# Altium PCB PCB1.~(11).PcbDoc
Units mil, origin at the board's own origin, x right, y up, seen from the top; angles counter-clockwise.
Board outline 2756 x 2756 mil, 4 copper layers (Top Layer, Internal Plane 1, Internal Plane 2, Bottom Layer), stack 18.2 mil thick; 14 components, 14 nets, 59 pads, 0 vias.
Unrouted connection lines stored in the file: 27.
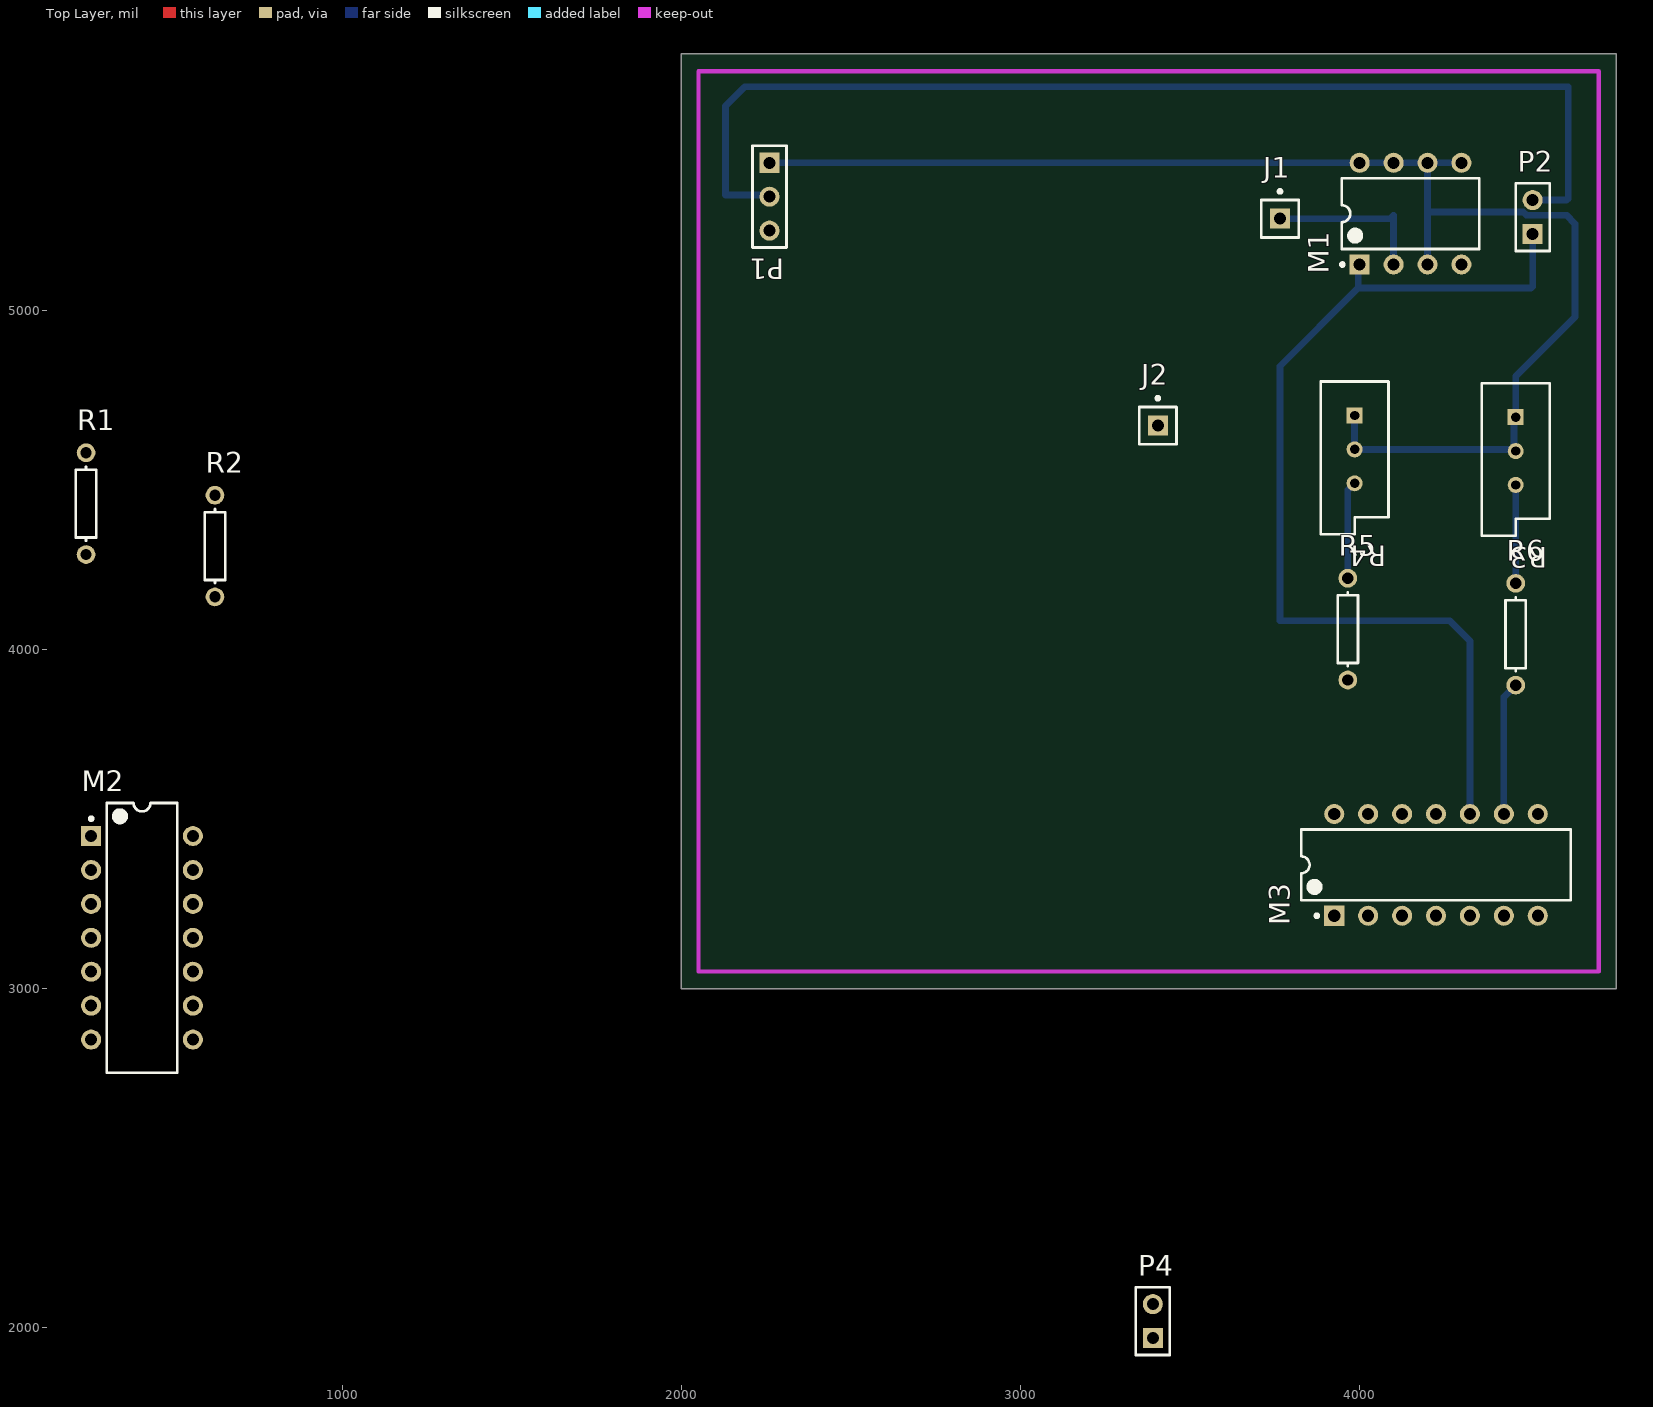
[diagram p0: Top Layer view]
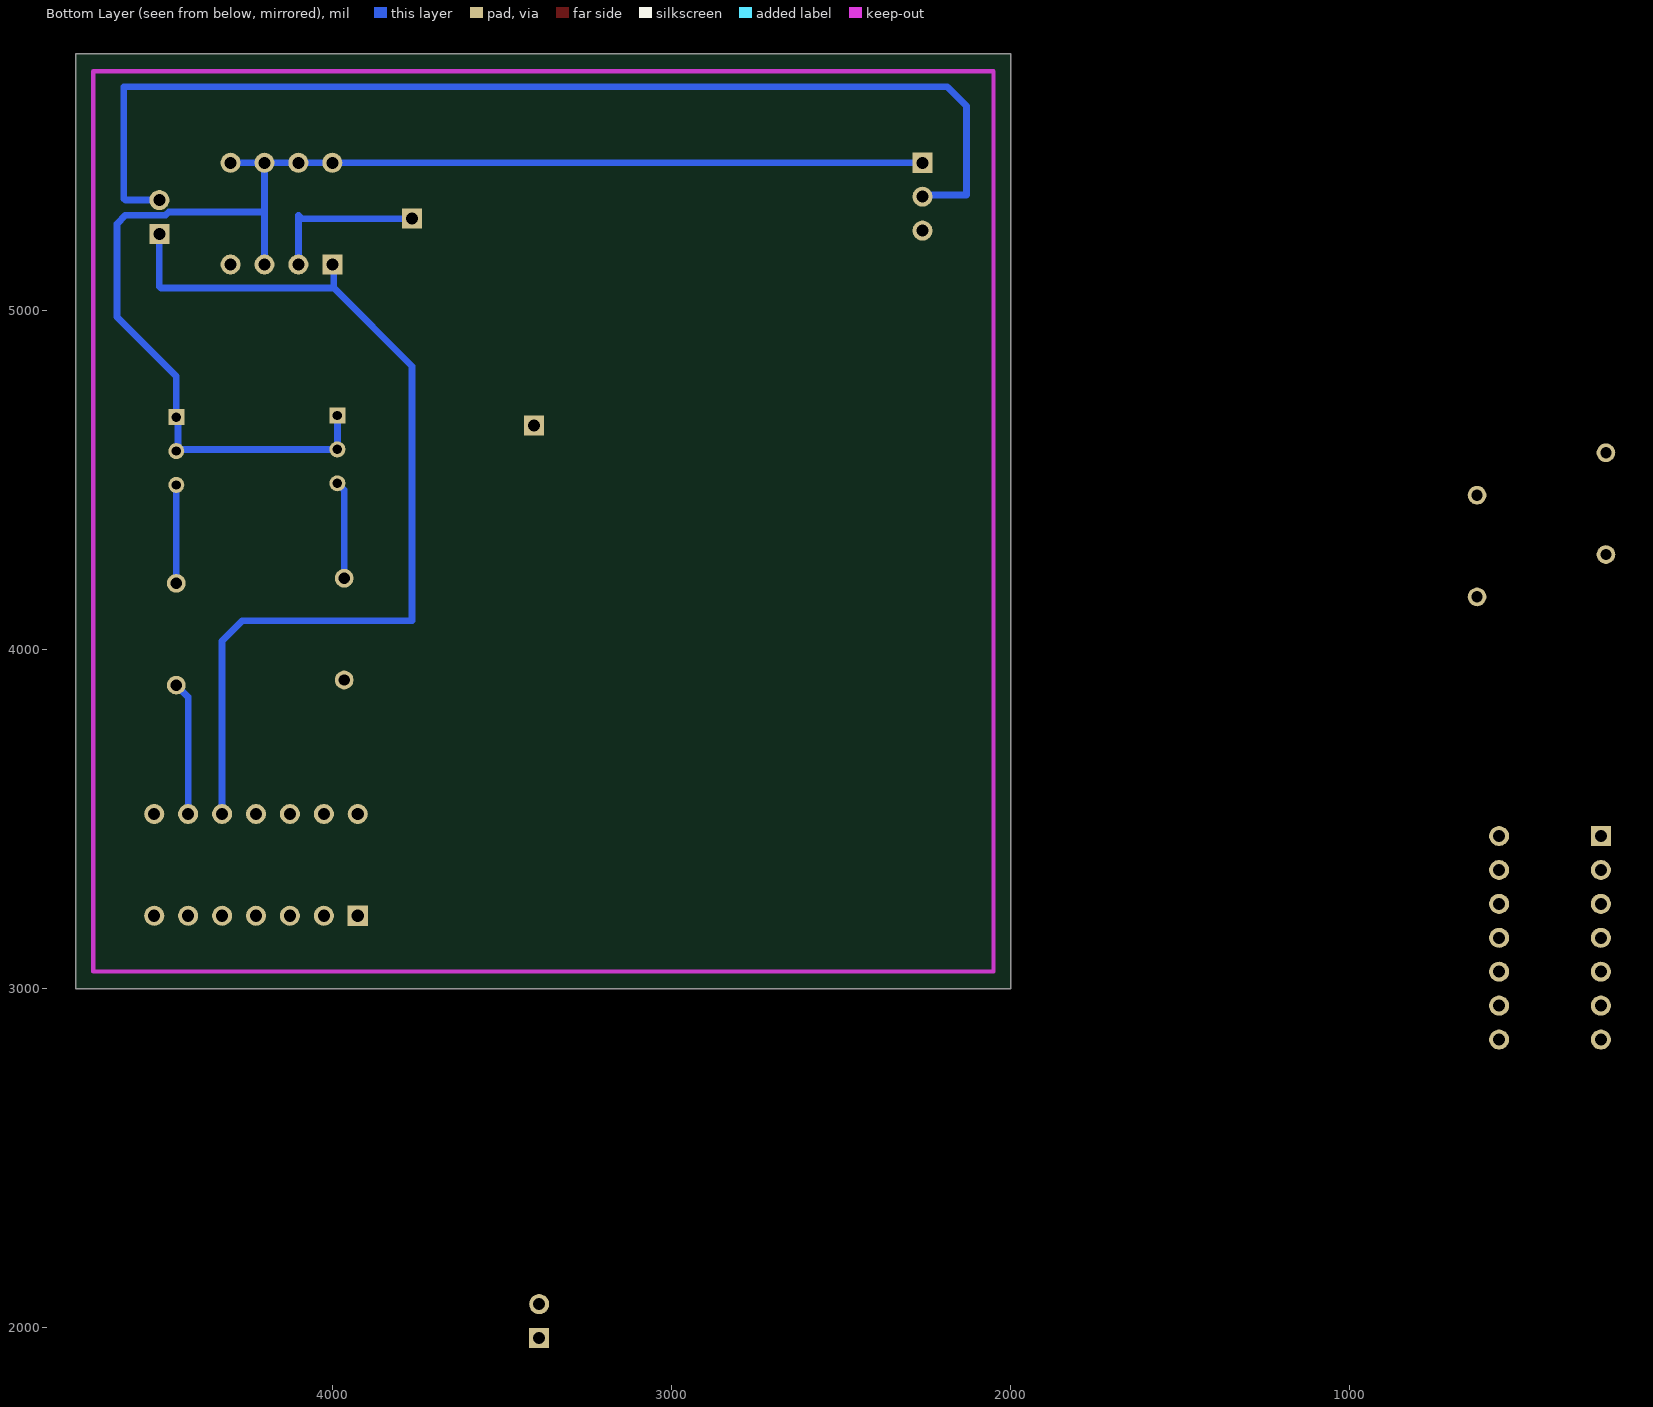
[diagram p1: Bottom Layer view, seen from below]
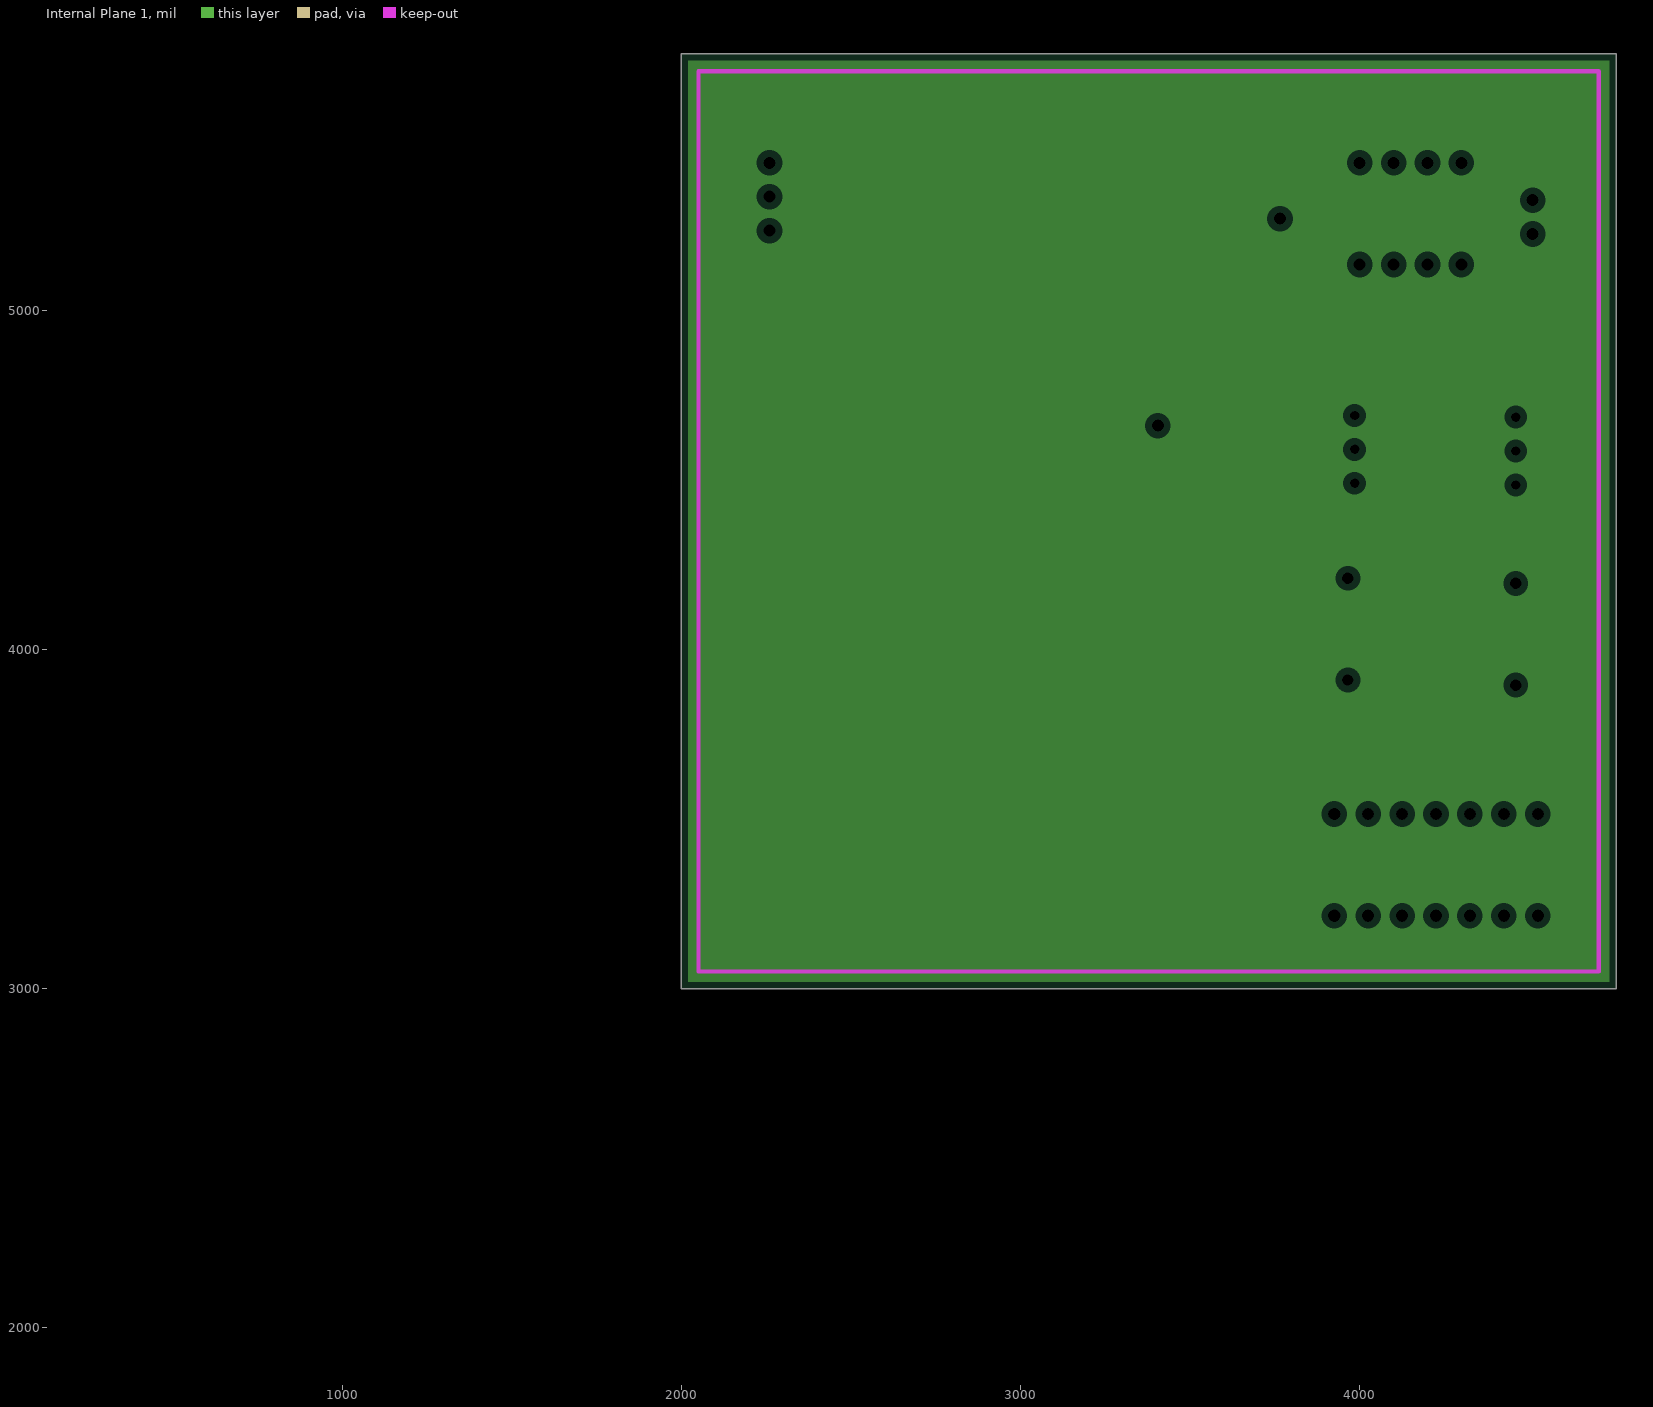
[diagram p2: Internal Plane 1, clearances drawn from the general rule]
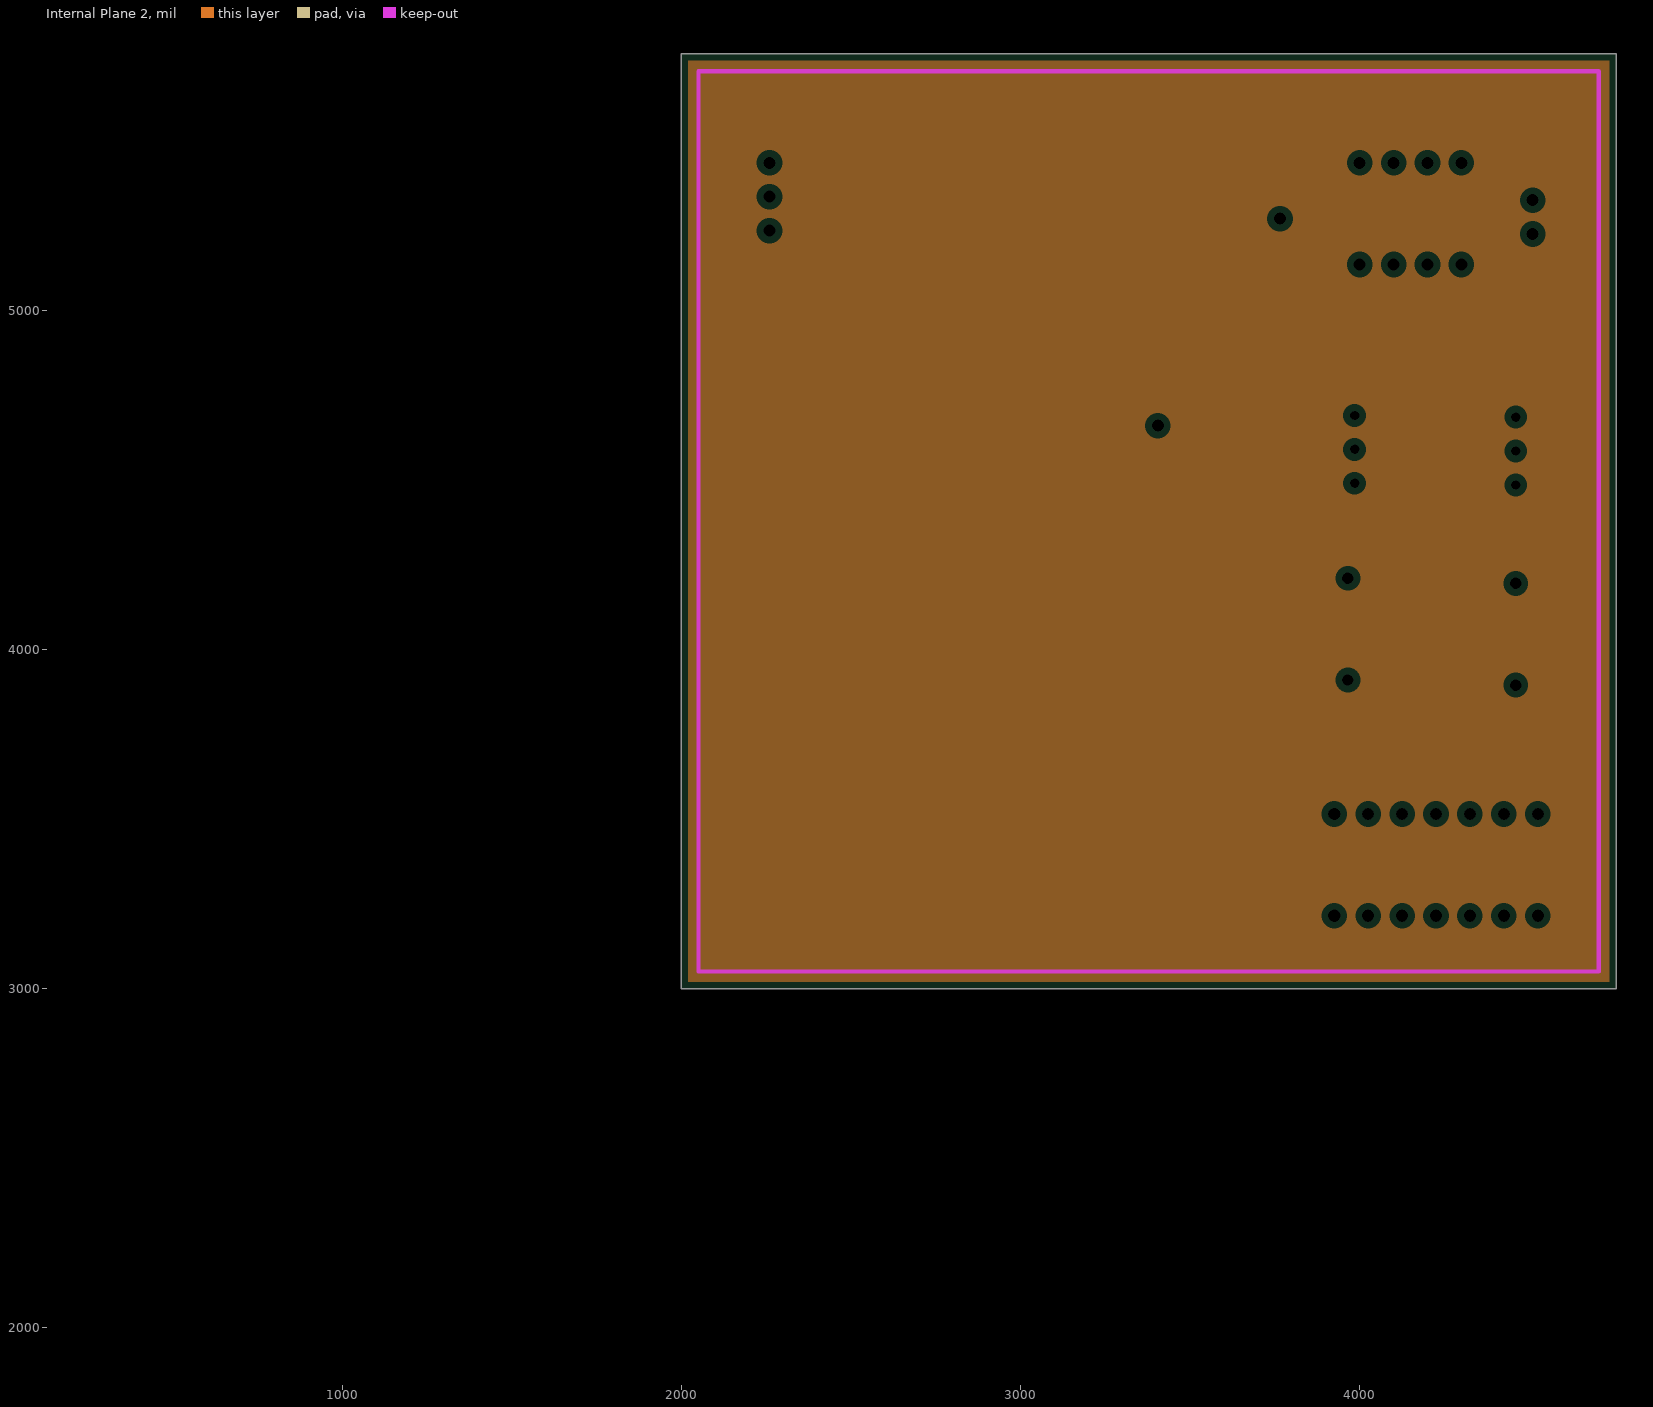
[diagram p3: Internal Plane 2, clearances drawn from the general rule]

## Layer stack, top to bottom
Top Solder: solder mask 0.4, Solder Resist, Dk 3.5
Top Layer: signal copper 1.4
Internal Plane 1: plane copper 1.4
Internal Plane 2: plane copper 1.4
Dielectric 1: dielectric 12.6, FR-4, Dk 4.8
Bottom Layer: signal copper 1.4
Bottom Solder: solder mask 0.4, Solder Resist, Dk 3.5

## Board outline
2000,3000 4756,3000 4756,5756 2000,5756

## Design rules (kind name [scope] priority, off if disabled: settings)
Clearance Clearance_1 [InNet('+5')] p1: gap=5
Clearance [All] p2: gap=30
PlaneClearance [All] p1: clearance=20
PlaneConnect [All] p1: planeconnectstyle=Relief reliefexpansion=20 reliefentries=4 reliefconductorwidth=10 reliefairgap=10
PolygonConnect [All] p1: connectstyle=Relief reliefconductorwidth=10 reliefentries=4 polygonreliefangle="90 Angle" airgapwidth=10
RoutingVias [All] p1: holewidth=32 width=62 viastyle="Through Hole" minholewidth=28 minwidth=50 maxholewidth=28 maxwidth=50
SolderMaskExpansion [All] p1: expansion=4
Width [All] p1: maxlimit=20 minlimit=8 preferedwidth=20 toplayer_minwidth=20 minimp=50.000000 maximp=50.000000 favimp=50.000000
28 further rules are at their usual default settings.

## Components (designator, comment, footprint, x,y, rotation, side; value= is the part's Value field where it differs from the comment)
J1 "Socket" PIN1 3765,5270 r0 top
J2 "Socket" PIN1 3405,4660 r0 top
M1 "ALD1117" DIP-8 4150,5285 r90 top
M2 "ALD1105" DIP-14 410,3150 r0 top
M3 "ALD1106" DIP-14 4225,3365 r90 top
P1 "Header 3" HDR1X3 2260,5435 r270 top
P2 "Header 2" HDR1X2 4510,5225 r90 top
P4 "Header 2" HDR1X2 3390,1970 r90 top
R1 "Res1" AXIAL-0.3 245,4430 r90 top
R2 "Res1" AXIAL-0.3 625,4305 r90 top
R3 "RPot" VR5 4460,4585 r270 top
R4 "RPot" VR5 3985,4590 r270 top
R5 "Res1" AXIAL-0.3 3965,4060 r90 top
R6 "Res1" AXIAL-0.3 4460,4045 r90 top

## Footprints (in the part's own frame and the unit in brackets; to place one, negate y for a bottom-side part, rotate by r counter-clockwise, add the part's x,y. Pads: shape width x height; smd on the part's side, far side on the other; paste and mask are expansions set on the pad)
AXIAL-0.3 [mm] "Axial Device, Thru-Hole; 2 Leads; 0.3 in Pin Spacing"
  round 1.4 hole 0.85: 1(-3.81,0) 2(3.81,0)
  silkscreen extent -2.77,-0.76 2.77,0.76
DIP-8 [mm] "DIP, 8-Pin, Row Spacing 7.62 mm, Pitch 2.54 mm"
  rect 1.5x1.5 hole 0.9: 1(-3.81,3.81)
  round 1.5 hole 0.9: 2(-3.81,1.27) 3(-3.81,-1.27) 4(-3.81,-3.81) 5(3.81,-3.81) 6(3.81,-1.27) 7(3.81,1.27) 8(3.81,3.81)
  silkscreen extent -3.93,-5.15 2.65,5.23, body extent -3.6,-5.15 3.6,5.15, height 5.33
DIP-14 [mm] "DIP, 14-Pin, Row Spacing 7.62 mm, Pitch 2.54 mm"
  rect 1.5x1.5 hole 0.9: 1(-3.81,7.62)
  round 1.5 hole 0.9: 2(-3.81,5.08) 3(-3.81,2.54) 4(-3.81,0) 5(-3.81,-2.54) 6(-3.81,-5.08) 7(-3.81,-7.62) 8(3.81,-7.62) 9(3.81,-5.08) 10(3.81,-2.54) 11(3.81,0) 12(3.81,2.54) 13(3.81,5.08) 14(3.81,7.62)
  silkscreen extent -3.93,-10.1 2.65,10.1, body extent -3.6,-10.1 3.6,10.1, height 5.08
HDR1X2 [mm] "Connector; Header; 2 Position"
  rect 1.5x1.5 hole 0.9: 1(0,0)
  round 1.5 hole 0.9: 2(2.54,0)
  silkscreen extent -1.27,-1.27 3.81,1.27
HDR1X3 [mm] "Connector; Header; 3 Position"
  rect 1.5x1.5 hole 0.9: 1(0,0)
  round 1.5 hole 0.9: 2(2.54,0) 3(5.08,0)
  silkscreen extent -1.27,-1.27 6.35,1.27
PIN1 [mm] "Connector; Plug"
  rect 1.5x1.5 hole 0.9: 1(0,0)
  silkscreen extent -1.4,-1.4 1.4,2.17
VR5 [mm] "Thru-Hole; 3 Leads"
  rect 1.2x1.2 hole 0.7: 1(-2.54,0)
  round 1.2 hole 0.7: 2(0,0) 3(2.54,0)
  silkscreen extent -5.08,-2.54 6.35,2.54

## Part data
M1: "Dual P-channel matched MOSFET array"
M2: "Dual P-channel and dual N-channel matched MOSFET array"
M3: "Quad N-channel matched MOSFET array"
P1: "Header, 3-Pin"
P2 P4: "Header, 2-Pin"
R1 R2 R5 R6: "Resistor"
R3 R4: "Potentiometer"

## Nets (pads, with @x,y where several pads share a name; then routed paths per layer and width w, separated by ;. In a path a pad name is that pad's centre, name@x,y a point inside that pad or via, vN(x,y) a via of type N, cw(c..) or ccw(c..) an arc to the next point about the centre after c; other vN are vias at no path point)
+5: M1.3 M1.5 M1.6 M1.7 M1.8 M2.7 M2.8 M2.11 P1.1 R3.1 R3.2 R4.1 R4.2 | length 4099.1
  Bottom Layer w20: P1.1 M1.8 M1.7 M1.6 ; R4.1 R4.2 4455,4590 4455,4680 R3.1 4460,4805 4635,4980 4635,5255 4609.53,5280.47 4491.56,5280.47 4482.03,5290 4200,5290 ; M1.3 4200,5290 ; M1.5 M1.6 ; 4200,5290 M1.6
-5: M3.3 M3.4 M3.7 M3.8 M3.12 P1.3
GND: P1.2 P2.2 R1.1 R2.1 | length 3338.7
  Bottom Layer w20: P1.2 2255,5340 2130,5340 2130,5602.09 2186.82,5658.91 4615,5658.91 4615,5330 4610,5325 P2.2
NetJ1_1: J1.1 M1.2 M2.5 M2.14 | length 484.1
  Bottom Layer w20: J1.1 4090,5270 4100,5280 M1.2
NetJ2_1: J2.1 M2.3 M2.4 M2.12 M3.14
NetM1_1: M1.1 M3.10 P2.1 | length 2913.6
  Bottom Layer w20: M1.1 3995.47,5130.47 3995.47,5065.47 ; M3.10 4325,4025 4265,4085 3765,4085 3765,4835 3995.47,5065.47 ; P2.1 4510,5070 4505.47,5065.47 3995.47,5065.47
NetM2_1: M2.1 M2.10
NetM2_2: M2.2 P4.1 R1.2
NetM2_6: M2.6 M2.9
NetM2_13: M2.13 P4.2 R2.2
NetM3_1: M3.1 M3.2 M3.13 R5.1
NetM3_5: M3.5 M3.6 M3.9 R6.1 | length 394.5
  Bottom Layer w20: M3.9 4425,3860 R6.1
NetR3_3: R3.3 R6.2 | length 290
  Bottom Layer w20: R6.2 R3.3
NetR4_3: R4.3 R5.2 | length 288.3
  Bottom Layer w20: R5.2 3965,4470 R4.3
pads on no net: M1.4 M3.11

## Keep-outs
Keep-Out Layer:
  lines w11.81: 2051.18,3051.18 4704.82,3051.18 4704.82,5704.82 2051.18,5704.82 2051.18,3051.18

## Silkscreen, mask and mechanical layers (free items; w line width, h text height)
Drill Drawing:
  text ".LEGEND" at 4956,3200 h60
  text "Drill Drawing." at 4956,3100 h60

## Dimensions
2051.18,3051.18 to 4704.82,3051.18 on Mechanical 1
2051.18,3051.18 to 2051.18,5704.82 on Mechanical 1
